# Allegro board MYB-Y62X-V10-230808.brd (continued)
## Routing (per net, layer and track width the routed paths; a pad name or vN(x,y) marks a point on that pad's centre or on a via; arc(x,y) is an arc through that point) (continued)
SOC_VOUT0_DATA12: length 75.7
  TOP w0.152: v2(137.71,47.5) 123.24,47.5 121.38,49.35 120.19,49.35 119.53,50.01 119.53,52.88 119.38,53.03 117.75,53.03 117.6,53.18 117.6,53.49 117.75,53.64 119.38,53.64 119.53,53.79 119.53,54.17 119.38,54.32 116.4,54.32 116.25,54.47 116.25,54.77 116.4,54.93 119.38,54.93 119.53,55.08 119.53,55.45 119.38,55.61 115.59,55.61 115.44,55.76 115.44,56.06 115.59,56.22 119.38,56.22 119.53,56.37 119.53,56.69 119.17,57.05 115.59,57.05 115.04,57.6 115.04,60.26 114.5,60.81 113.1,60.81 112.67,61.24 112.67,62 112.34,62.33 111.77,62.33 111.62,62.49 111.62,63.42 111.47,63.58 111.16,63.58 111.01,63.42 111.01,62.49 110.86,62.33 110.55,62.33 110.4,62.49 110.4,63.42 110.25,63.58 109.94,63.58 109.79,63.42 109.79,62.49 109.64,62.33 U43.97 ; R175.1 144.7,39.62 144.45,39.88 v2(143.43,39.88)
  BOTTOM w0.152: v2(143.43,39.88) 143.43,40.77 137.71,46.48 v2(137.71,47.5)
SOC_VOUT0_DATA13: length 76.9
  TOP w0.152: R176.1 145.59,41.27 144.95,41.91 142.97,41.91 142.81,42.06 142.81,42.65 142.66,42.8 142.36,42.8 142.2,42.65 142.2,42.06 142.05,41.91 141.75,41.91 141.59,42.06 141.59,42.65 141.44,42.8 141.14,42.8 140.98,42.65 140.98,42.06 140.83,41.91 140.53,41.91 140.37,42.06 140.37,42.65 140.22,42.8 139.92,42.8 139.77,42.65 139.77,42.06 139.61,41.91 139.31,41.91 139.16,42.06 139.16,42.65 139,42.8 138.7,42.8 138.55,42.65 138.55,42.06 138.39,41.91 138.09,41.91 137.94,42.06 137.94,42.65 137.78,42.8 137.11,42.8 136.95,42.65 v2(136.95,39.75) ; U43.L30 v2(106.6,52.32)
  BOTTOM w0.152: v2(106.6,52.32) 106.09,52.83 106.09,53.59 106.73,54.23 108.25,54.23 110.41,56.39 111.94,56.39 112.09,56.54 112.09,57.56 112.24,57.71 112.55,57.71 112.7,57.56 112.7,56.54 112.85,56.39 113.81,56.39 113.96,56.54 113.96,56.74 114.11,56.9 114.42,56.9 114.57,56.74 114.57,56.54 114.72,56.39 115.02,56.39 115.18,56.54 115.18,56.74 115.33,56.9 115.63,56.9 115.79,56.74 115.79,56.54 115.94,56.39 116.24,56.39 116.4,56.54 116.4,56.74 116.55,56.9 116.85,56.9 117.01,56.74 117.01,56.54 117.16,56.39 117.62,56.39 118.21,55.8 119.5,55.8 120.93,54.38 120.93,52.2 121.08,52.04 125.12,52.04 125.28,51.89 125.28,51.38 125.43,51.23 127.81,51.23 128.18,50.86 128.18,47.9 128.33,47.74 129,47.74 129.16,47.59 129.16,47.29 129,47.13 128.33,47.13 128.18,46.98 128.18,46.68 128.33,46.52 129,46.52 129.16,46.37 129.16,46.07 129,45.91 128.33,45.91 128.18,45.76 128.18,45.07 132.36,40.89 135.81,40.89 v2(136.95,39.75)
SOC_VOUT0_DATA14: length 75.3
  TOP w0.152: R177.1 v2(146.48,39.62) ; U43.94 112.67,59.33 113.97,58.04 113.97,54.64 117.14,51.46 117.98,51.46 118.13,51.31 118.13,46.78 118.76,46.15 118.76,45.39 118.91,45.24 119.22,45.24 119.37,45.39 119.37,46.15 119.52,46.3 119.83,46.3 119.98,46.15 119.98,45.39 120.13,45.24 120.44,45.24 120.59,45.39 120.59,46.15 120.74,46.3 121.05,46.3 121.2,46.15 121.2,45.39 121.35,45.24 121.66,45.24 121.81,45.39 121.81,46.15 121.96,46.3 122.26,46.3 122.42,46.15 122.42,45.39 122.57,45.24 122.87,45.24 123.03,45.39 123.03,46.15 123.18,46.3 123.48,46.3 123.64,46.15 123.64,45.39 123.79,45.24 124.09,45.24 124.25,45.39 124.25,46.15 124.4,46.3 124.7,46.3 124.86,46.15 124.86,45.39 125.01,45.24 125.31,45.24 125.47,45.39 125.47,46.15 125.62,46.3 125.92,46.3 126.07,46.15 126.07,45.39 126.23,45.24 126.53,45.24 126.68,45.39 126.68,46.15 126.84,46.3 127.14,46.3 127.29,46.15 127.29,45.39 127.45,45.24 127.75,45.24 127.9,45.39 127.9,46.15 128.06,46.3 128.36,46.3 128.51,46.15 128.51,45.39 128.67,45.24 128.97,45.24 129.12,45.39 129.12,46.15 129.28,46.3 129.58,46.3 129.73,46.15 129.73,45.39 129.88,45.24 130.19,45.24 130.34,45.39 130.34,46.15 130.49,46.3 130.8,46.3 130.95,46.15 130.95,45.39 131.1,45.24 131.41,45.24 131.56,45.39 131.56,46.15 131.71,46.3 132.02,46.3 132.17,46.15 132.17,45.39 132.32,45.24 132.63,45.24 132.78,45.39 132.78,46.15 132.93,46.3 133.24,46.3 133.39,46.15 133.39,45.39 133.54,45.24 134.24,45.24 134.39,45.39 134.39,46.02 134.84,46.48 v2(138.48,46.48)
  BOTTOM w0.152: v2(146.48,39.62) 145.33,39.62 v2(138.48,46.48)
SOC_VOUT0_DATA15: length 74.4
  TOP w0.152: R178.1 147.37,41.05 145.03,43.38 142.97,43.38 142.82,43.54 142.82,44.25 142.66,44.4 142.36,44.4 142.21,44.25 142.21,43.54 142.06,43.38 141.75,43.38 141.6,43.54 141.6,44.25 141.45,44.4 141.14,44.4 140.99,44.25 140.99,43.54 140.84,43.38 140.53,43.38 140.38,43.54 140.38,44.25 140.23,44.4 139.92,44.4 139.77,44.25 139.77,43.54 139.62,43.38 139.31,43.38 139.16,43.54 139.16,44.25 139.01,44.4 136.7,44.4 135.68,43.38 v2(135.68,39.75) ; U43.L28 99.87,48.9 v2(104.57,48.9)
  BOTTOM w0.152: v2(104.57,48.9) 111.04,55.37 116.18,55.37 116.71,54.84 118.97,54.84 119.93,53.87 119.93,51.61 120.46,51.08 124,51.08 124.94,50.14 125.57,50.14 125.88,49.83 125.88,47.96 126.85,46.99 126.85,44.93 132.03,39.75 v2(135.68,39.75)
SOC_VOUT0_DATA16/BOOTMODE08: length 75
  TOP w0.152: R179.1 v2(148.26,40.01) R197.1 ; v2(120.82,74.8) 114.73,74.8 109.2,80.33 U43.115
  BOTTOM w0.152: v2(148.26,40.01) 148.13,40.13 145.46,40.13 139.24,46.35 139.24,46.74 134.29,51.69 134.29,58.72 128.29,64.72 128.29,66.73 127.73,67.28 125.98,67.28 125.13,68.14 124.84,68.14 124.68,68.29 124.68,69.44 124.53,69.6 124.23,69.6 124.08,69.44 124.08,68.29 123.92,68.14 123.62,68.14 123.47,68.29 123.47,69.44 123.31,69.6 123.01,69.6 122.86,69.44 122.86,68.29 122.7,68.14 122.4,68.14 122.25,68.29 122.25,69.44 122.09,69.6 121.79,69.6 121.64,69.44 121.64,68.66 121.43,68.45 121.13,68.45 120.82,68.76 v2(120.82,74.8)
SOC_VOUT0_DATA17/BOOTMODE09: length 74.9
  TOP w0.152: R199.1 v2(149.27,40.01) R180.1 ; U43.113 109.16,78.33 113.2,74.3 v2(121.71,74.3)
  BOTTOM w0.152: v2(149.27,40.01) 148.76,40.51 145.67,40.51 139.67,46.51 139.67,46.94 134.79,51.82 134.79,58.96 128.75,65 128.75,67.72 128.01,68.45 125.6,68.45 125.32,68.73 125.32,69.85 125.07,70.1 121.87,70.1 121.71,70.26 121.71,70.57 121.87,70.72 125.19,70.72 125.35,70.88 125.35,71.18 125.19,71.33 121.87,71.33 121.71,71.49 v2(121.71,74.3)
SOC_VOUT0_DATA18/BOOTMODE10: length 74
  TOP w0.152: v2(122.6,73.79) 112.7,73.79 109.15,77.33 U43.112 ; R181.1 v2(150.29,40.01) R200.1
  BOTTOM w0.152: v2(122.6,73.79) 122.6,72.72 123.44,71.88 125.83,71.88 125.98,71.73 125.98,71.09 126.13,70.94 126.69,70.94 126.84,70.78 126.84,70.48 126.69,70.33 126.13,70.33 125.98,70.18 125.98,69.11 126.16,68.94 128.34,68.94 129.16,68.12 129.16,65.43 133.52,61.06 133.74,61.06 134.09,61.42 134.31,61.42 134.52,61.2 134.52,60.99 134.17,60.63 134.17,60.42 135.23,59.35 135.23,52.01 135.63,51.62 135.84,51.62 136.01,51.78 136.22,51.78 136.44,51.57 136.44,51.35 136.27,51.19 136.27,50.97 136.49,50.76 136.7,50.76 136.87,50.92 137.09,50.92 137.3,50.71 137.3,50.49 137.14,50.32 137.14,50.11 137.35,49.89 137.57,49.89 137.73,50.06 137.95,50.06 138.16,49.84 138.16,49.63 138,49.46 138,49.25 138.21,49.03 138.43,49.03 138.6,49.2 138.81,49.2 139.03,48.98 139.03,48.76 138.86,48.6 138.86,48.38 139.08,48.17 139.29,48.17 139.46,48.33 139.67,48.33 139.89,48.12 139.89,47.9 139.72,47.74 139.72,47.52 140.2,47.04 140.2,46.61 145.79,41.02 149.27,41.02 v2(150.29,40.01)
SOC_VOUT0_DATA19/BOOTMODE11: length 77.2
  TOP w0.152: U43.116 108.96,81.33 114.98,75.31 121.71,75.31 v2(123.24,73.79) ; R182.1 v2(151.3,40.01) R201.1
  BOTTOM w0.152: v2(123.24,73.79) 123.24,72.77 123.59,72.42 127.28,72.42 127.81,71.88 127.81,71.17 127.4,70.76 127.4,69.98 127.78,69.6 128.44,69.6 130.18,67.86 130.18,66.15 129.81,65.78 129.81,65.56 130.03,65.35 130.24,65.35 130.61,65.72 130.82,65.72 131.04,65.5 131.04,65.29 130.67,64.92 130.67,64.7 130.89,64.49 131.1,64.49 131.47,64.85 131.69,64.85 131.9,64.64 131.9,64.42 131.53,64.05 131.53,63.84 131.75,63.62 131.97,63.62 132.33,63.99 132.55,63.99 132.77,63.78 132.77,63.56 132.4,63.19 132.4,62.98 132.61,62.76 132.83,62.76 133.2,63.13 133.41,63.13 133.63,62.91 133.63,62.7 133.26,62.33 133.26,62.11 133.48,61.9 133.69,61.9 134.06,62.27 134.28,62.27 135.68,60.86 135.68,53.04 140.61,48.11 140.61,46.79 146,41.4 149.91,41.4 v2(151.3,40.01)
SOC_VOUT0_DATA20/BOOTMODE12: length 72
  TOP w0.152: R202.1 v2(152.32,40.01) R183.1 ; v2(141.04,46.99) 121.77,46.99 121.6,47.17 121.6,48.64 121.44,48.79 121.14,48.79 120.99,48.64 120.99,47.14 120.83,46.99 120.56,46.99 120.38,47.17 120.38,48.64 120.22,48.79 119.92,48.79 119.77,48.64 119.77,47.14 119.62,46.99 119.12,46.99 118.84,47.27 118.84,51.92 118.51,52.25 117.29,52.25 114.5,55.04 114.5,59.56 113.86,60.2 112.11,60.2 111.96,60.35 111.96,61.42 111.81,61.57 111.5,61.57 111.35,61.42 111.35,60.35 111.2,60.2 110.87,60.2 110.71,60.35 110.71,61.42 110.56,61.57 110.26,61.57 110.1,61.42 110.1,60.35 109.95,60.2 109.55,60.2 109.39,60.35 109.39,61.21 109.27,61.33 U43.96
  BOTTOM w0.152: v2(141.04,46.99) 142.08,45.95 142.82,45.95 146.99,41.78 150.54,41.78 v2(152.32,40.01)
SOC_VOUT0_DATA21/BOOTMODE13: length 73.8
  TOP w0.152: v2(129.21,72.39) 128.7,72.9 111.17,72.9 110.16,71.88 110.16,69.34 109.15,68.33 U43.103 ; R184.1 v2(153.34,40.01) R203.1
  BOTTOM w0.152: v2(129.21,72.39) 130.98,70.61 130.98,68.91 131.14,68.76 132.13,68.76 132.28,68.6 132.28,68.3 132.13,68.15 131.57,68.15 131.42,67.99 131.42,66.7 136.7,61.42 136.7,53.38 147.41,42.67 152.98,42.67 153.34,42.32 v2(153.34,40.01)
SOC_VOUT0_DATA22/BOOTMODE14: length 71.9
  TOP w0.152: v2(129.84,72.39) 128.9,73.33 U43.108 ; R185.1 v2(154.35,40.01) R204.1
  BOTTOM w0.152: v2(154.35,40.01) 154.35,42.65 153.82,43.18 147.62,43.18 137.21,53.59 137.21,61.59 132.91,65.89 132.91,66.5 132.76,66.66 132.1,66.66 131.95,66.81 131.95,67.11 132.1,67.27 132.76,67.27 132.91,67.42 132.91,68.88 132.42,69.38 132.05,69.38 131.62,69.81 131.62,70.61 v2(129.84,72.39)
SOC_VOUT0_DATA23/BOOTMODE15: length 73.6
  TOP w0.152: v2(128.57,72.39) 111.55,72.39 110.66,71.5 110.66,68.96 109.04,67.33 U43.102 ; R186.1 v2(155.37,40.01) R205.1
  BOTTOM w0.152: v2(155.37,40.01) 154.83,39.47 153.13,39.47 152.83,39.78 152.83,40.26 150.8,42.29 147.13,42.29 136.23,53.19 136.23,61.1 130.83,66.5 130.83,68.05 130.35,68.53 130.35,70.61 v2(128.57,72.39)
SOC_VOUT0_DE: length 72.9
  TOP w0.152: v2(112.59,52.86) 109.65,52.86 109.12,52.33 U43.87 ; R194.1 v2(140,26.54)
  BOTTOM w0.152: v2(140,26.54) 138.07,26.54 137.89,26.72 137.89,32.49 137.51,32.87 136.29,32.87 133.88,35.28 133.88,36.83 133.68,37.03 130.73,37.03 130.5,37.26 130.5,38.53 130.3,38.73 129.36,38.73 129.03,39.07 129.03,40.44 125.09,44.37 125.09,45.87 123.95,47.02 123.95,47.63 123.8,47.78 123.42,47.78 123.27,47.63 123.27,47.32 123.12,47.17 122.81,47.17 122.66,47.32 122.66,47.63 122.51,47.78 122.2,47.78 122.05,47.63 122.05,47.32 121.9,47.17 121.59,47.17 121.44,47.32 121.44,47.63 121.29,47.78 120.98,47.78 120.83,47.63 120.83,47.32 120.68,47.17 120.37,47.17 120.22,47.32 120.22,47.63 120.04,47.8 118.97,47.8 118.82,47.96 118.82,48.26 118.97,48.41 123.8,48.41 123.95,48.57 123.95,48.82 123.8,48.97 123.37,48.97 123.22,49.12 123.22,49.38 123.07,49.53 122.76,49.53 122.61,49.38 122.61,49.12 122.46,48.97 122.15,48.97 122,49.12 122,49.38 121.85,49.53 121.54,49.53 121.39,49.38 121.39,49.12 121.24,48.97 120.93,48.97 120.78,49.12 120.78,49.38 120.63,49.53 120.32,49.53 120.17,49.38 120.17,49.12 120.02,48.97 118.16,48.97 117.73,49.4 117.73,53.02 117.57,53.17 116.04,53.17 115.36,53.85 111.25,53.85 111.1,53.7 111.1,53.01 111.25,52.86 v2(112.59,52.86)
SOC_VOUT0_HSYNC: length 74
  TOP w0.152: R196.1 v2(140,25.65) ; U43.88 v2(113.71,53.33)
  BOTTOM w0.152: v2(113.71,53.33) 115.34,53.33 116.02,52.65 116.91,52.65 117.06,52.5 117.06,47.14 117.7,46.51 119.64,46.51 119.79,46.35 119.79,45.57 119.94,45.42 120.25,45.42 120.4,45.57 120.4,46.33 120.58,46.51 120.86,46.51 121.01,46.35 121.01,45.57 121.16,45.42 121.47,45.42 121.62,45.57 121.62,46.33 121.8,46.51 122.08,46.51 122.23,46.35 122.23,45.57 122.38,45.42 122.69,45.42 122.84,45.57 122.84,46.33 123.02,46.51 123.57,46.51 123.95,46.13 123.95,44.72 128.24,40.43 128.24,40.06 128.09,39.91 126.51,39.91 126.36,39.76 126.36,39.45 126.51,39.3 127.96,39.3 128.6,38.66 128.6,36.7 128.75,36.55 129.1,36.55 129.25,36.7 129.25,38.13 129.4,38.28 129.71,38.28 129.86,38.13 129.86,36.7 130.01,36.55 132.71,36.55 133.27,35.99 133.27,35.18 136.14,32.31 136.98,32.31 137.46,31.83 137.46,25.76 137.21,25.5 134.31,25.5 134.16,25.35 134.16,24.79 134.31,24.64 137.44,24.64 137.97,25.17 139.52,25.17 v2(140,25.65)
SOC_VOUT0_PCLK: length 73.1
  TOP w0.152: U43.89 v2(112.7,54.33) ; R198.1 139.21,35.43 139.05,35.28 139.05,35 138.9,34.85 138.6,34.85 138.42,35.03 138.42,35.59 138.27,35.74 137.86,35.74 137.71,35.59 137.71,34.82 137.55,34.67 137.27,34.67 137.05,34.9 137.05,36.73 137.2,36.88 139.47,36.88 139.65,37.06 139.65,37.41 139.5,37.57 136.55,37.57 136.39,37.41 136.39,33.6 136.24,33.45 135.94,33.45 135.76,33.63 135.76,37.44 135.61,37.59 135.3,37.59 135.15,37.44 135.15,33.6 135,33.45 134.57,33.45 134.41,33.6 v2(134.41,35.43)
  BOTTOM w0.152: v2(134.41,35.43) 134.44,35.46 134.44,38.2 134.29,38.35 131.87,38.35 125.62,44.6 125.62,46.2 124.53,47.29 124.53,48.97 123.55,49.95 119.55,49.95 119.11,49.5 118.31,49.5 118.16,49.66 118.16,51.3 118.31,51.45 118.87,51.45 119.02,51.6 119.02,51.91 118.87,52.06 118.31,52.06 118.16,52.21 118.16,52.52 118.31,52.67 118.87,52.67 119.02,52.82 119.02,53.26 118.59,53.7 116.15,53.7 115.51,54.33 v2(112.7,54.33)
SOC_VOUT0_VSYNC: length 74.1
  TOP w0.152: v2(114.85,52.83) 112.35,55.33 U43.90 ; R195.1 v2(140,24.77)
  BOTTOM w0.152: v2(140,24.77) 138.3,24.77 137.74,24.21 134.01,24.21 133.68,24.54 133.68,25.73 134.01,26.06 136.6,26.06 137.08,26.54 137.08,31.29 136.6,31.78 133.55,31.78 132.85,32.48 132.85,34.91 132.19,35.56 125.73,35.56 125.22,36.07 125.22,36.61 125.37,36.76 127.12,36.76 127.28,36.92 127.28,37.22 127.12,37.37 125.37,37.37 125.22,37.53 125.22,37.83 125.37,37.98 127.12,37.98 127.28,38.14 127.28,38.44 127.12,38.59 125.37,38.59 125.22,38.75 125.22,40.59 125.37,40.74 126.49,40.74 126.64,40.9 126.64,41.2 126.49,41.35 125.37,41.35 125.22,41.51 125.22,42.38 122.69,44.91 118.28,44.91 116.53,46.66 116.53,51.16 v2(114.85,52.83)
SOC_WKUP_UART0_RXD: length 216
  TOP w0.152: v2(79.8,49.28) 79.8,49.63 79.65,49.78 U43.L20 ; U46.8 17.03,110.35 17.29,110.08 v2(17.29,105.51)
  ART03 w0.152: v2(114.73,81.28) 114.85,81.15 119.81,81.15 125.6,86.94 125.6,89.33 124.56,90.37 120.64,90.37 119.81,89.53 113.58,89.53 111.81,91.31 111.81,92.63 110.44,94.01 108.86,94.01 105.71,97.16 103.9,97.16 97.89,103.17 97.89,106.48 94.53,109.83 94.53,112.52 93.65,113.41 65.07,113.41 62.02,110.36 33.96,110.36 29.1,105.51 v2(17.29,105.51) ; v2(79.8,49.28) 90.8,49.28 91.87,48.21 102.36,48.21 105.08,50.93 105.08,72.06 104.42,72.72 104.42,78.21 v2(105.71,79.5)
  BOTTOM w0.152: v2(114.73,81.28) 113.58,80.14 106.35,80.14 v2(105.71,79.5)
SOC_WKUP_UART0_TXD: length 191.7
  TOP w0.152: v2(105.61,55.7) 105.61,53.87 U43.L31 ; v2(17.98,106.07) 17.98,110.52 17.5,111 14.65,111 14.01,110.35 U46.1
  ART03 w0.152: v2(17.98,106.07) 28.77,106.07 33.83,111.12 61.9,111.12 64.69,113.92 94.05,113.92 95.12,112.85 95.12,110.13 98.52,106.73 98.52,103.2 104.06,97.66 105.84,97.66 108.99,94.51 111.02,94.51 112.57,92.96 112.57,91.44 113.84,90.17 119.68,90.17 120.44,90.93 124.76,90.93 126.13,89.56 v2(126.13,78.46)
  BOTTOM w0.152: v2(126.13,78.46) 125.78,78.11 111.96,78.11 108.07,74.22 108.07,73.23 105.05,70.2 105.05,56.27 v2(105.61,55.7)
USB0CC1: length 8.4
  TOP w0.203: 57.83,17.14 58.01,17.33 U29.1
  TOP w0.254: 57.83,17.14 57.58,16.89 54.91,16.89 54.4,16.38 54.4,14.8 54.15,14.55 C158.1 53.66,14.53 R314.1
USB0CC2: length 5.6
  TOP w0.203: U29.2 58.41,17.45
  TOP w0.254: R315.1 C160.1 57.83,14.55 57.58,14.8 57.58,16 58.41,16.84 58.41,17.45
USB_5G_DM: length 130.6
  TOP w0.155: U28.17 130.11,24.45 130.19,24.36 130.19,24.15 129.53,23.48 128.03,23.48 127.39,24.12 127.39,24.98 126.95,25.42 125.82,25.42 v2(125.65,25.59)
  ART03 w0.137: v2(28.66,43.81) 28.49,43.65 28.49,43.47 28.63,43.33 34.23,43.33 34.71,43.81 36.08,43.81 36.23,43.97 36.62,43.97 36.78,43.81 37.19,43.81 37.34,43.97 37.74,43.97 37.89,43.81 38.29,43.81 38.44,43.97 38.84,43.97 38.99,43.81 39.16,43.81 39.34,43.99 39.71,43.99 39.89,43.81 40.26,43.81 40.44,43.99 40.81,43.99 40.98,43.81 41.35,43.81 41.53,43.99 41.9,43.99 42.08,43.81 44.65,43.81 44.8,43.97 45.2,43.97 45.35,43.81 45.75,43.81 45.9,43.97 46.3,43.97 46.45,43.81 57.1,43.81 59.25,45.97 61.95,45.97 63.8,44.12 63.8,37.21 65.23,35.79 73.34,35.79 75.5,37.95 80.67,37.95 82.22,36.4 88.72,36.4 89.38,35.74 96.39,35.74 96.97,36.32 99.36,36.32 100.38,35.31 110.16,35.31 110.89,34.57 110.89,33.4 111.1,33.2 118.69,33.2 125.04,26.85 125.04,25.56 125.18,25.42 125.49,25.42 v2(125.65,25.59)
  BOTTOM w0.155: v2(28.66,43.81) 28.49,43.98 28.49,46.74 29.41,47.65 29.41,49.29 29.5,49.38 J19.9
USB_5G_DP: length 130.7
  TOP w0.155: U28.18 130.61,24.45 130.52,24.36 130.52,24.01 129.67,23.16 127.89,23.16 127.07,23.98 127.07,24.84 126.81,25.1 125.82,25.1 v2(125.65,24.93)
  ART03 w0.137: v2(125.65,24.93) 125.49,25.1 125.04,25.1 124.71,25.42 124.71,26.71 118.55,32.87 110.96,32.87 110.56,33.27 110.56,34.43 110.02,34.98 100.24,34.98 99.23,35.99 97.11,35.99 96.52,35.41 89.25,35.41 88.58,36.07 82.09,36.07 80.54,37.62 75.64,37.62 73.48,35.46 65.09,35.46 63.47,37.08 63.47,43.98 61.81,45.65 59.39,45.65 57.23,43.49 34.85,43.49 34.36,43 28.5,43 28.17,43.33 28.17,43.65 v2(28,43.81)
  BOTTOM w0.155: v2(28,43.81) 28.17,43.98 28.17,46.87 29.09,47.79 29.09,49.29 29,49.38 J19.7
USB_HUB_RST: length 45.7
  TOP w0.152: v2(138.98,31.24) 138.41,31.24 R487.1 ; U42.6 137.02,67.64 135.94,66.55 135.94,63.25 v2(138.86,60.33)
  ART03 w0.152: v2(138.98,31.24) 139.49,31.75 139.49,33.15 138.86,33.78 138.86,34.92 140.38,36.45 140.38,42.95 143.68,46.25 v2(143.68,47.78)
  BOTTOM w0.152: v2(143.68,47.78) 138.86,52.6 v2(138.86,60.33)
USB_I2C_SCL: length 2.3
  TOP w0.152: U29.8 58.01,20.08 v2(57.77,20.32) R454.2
  BOTTOM w0.152: R454.2 v2(57.77,20.32)
USB_I2C_SDA: length 2.3
  TOP w0.152: R494.2 v2(58.66,20.32) 58.41,20.08 U29.7
  BOTTOM w0.152: R494.2 v2(58.66,20.32)
USB_UART_DM: length 4.8
  TOP w0.155: U19.4 71.36,17.19 71.27,17.11 71.27,14.03 71.61,13.69 L6.1
USB_UART_DP: length 4.8
  TOP w0.155: U19.3 70.86,17.19 70.94,17.11 70.94,14.03 70.61,13.69 L6.4
USBA0_DM: length 11.8
  TOP w0.155: J16.A2 133.5,15.94 133.5,17.69 133.17,18.03 133.17,19.6 D27.2 133.17,20.67 133.17,22.24 131.69,23.72 131.69,24.36 131.61,24.45 U28.20
USBA0_DP: length 11.8
  TOP w0.155: U28.21 132.11,24.45 132.02,24.36 132.02,23.85 133.5,22.38 133.5,20.67 D28.2 133.5,19.6 133.5,18.16 133.83,17.83 133.83,15.94 J16.A3
USBA1_DM: length 17.1
  TOP w0.155: J16.B2 133.5,13.32 133.5,13.7 133.85,14.04 135.56,14.04 135.74,14.23 135.74,19.6 D30.2 135.77,20.7 135.77,22.31 135.04,23.04 134.16,23.04 133.19,24.01 133.19,24.36 133.11,24.45 U28.23
USBA1_DP: length 17.1
  TOP w0.155: J16.B3 133.83,13.32 133.83,13.56 133.98,13.72 135.69,13.72 136.07,14.09 136.07,19.6 D29.2 136.09,20.64 136.09,22.45 135.18,23.37 134.3,23.37 133.52,24.15 133.52,24.36 133.61,24.45 U28.24
USBC_ID: length 15.5
  TOP w0.152: v2(55.99,20.32) R309.2 56.82,19.56 56.98,19.4 U29.9 ; v2(61.13,27.05) 61.13,28.65 60.76,29.02 R319.1
  ART03 w0.152: v2(61.13,27.05) 59.31,27.05 58.09,25.83 58.09,24.64 55.99,22.54 v2(55.99,20.32)
USER_LED: length 92.3
  TOP w0.152: v2(127.85,79.12) 129.4,77.57 137.66,77.57 142.62,72.62 142.62,67.74 141.21,66.33 U42.8 ; D54.2 v2(97.84,116.08)
  ART03 w0.152: v2(127.85,79.12) 128.44,79.72 128.44,87.88 131.24,90.68 131.24,93.73 128.82,96.14 108.81,96.14 105.41,99.54 103.5,99.54 99.77,103.28 99.77,107.01 97.84,108.94 v2(97.84,116.08)
USIM1_CLK: length 79.9
  ART03 w0.152: v2(63.57,102.21) 55.27,102.21 51.71,98.65 51.71,80.14 50.75,79.17 v2(50.75,76.23)
  BOTTOM w0.152: J19.32 35.25,62.65 38.49,65.9 48.04,65.9 48.75,66.61 48.75,75.47 49.5,76.23 v2(50.75,76.23) ; v2(63.57,102.21) 64.87,100.91 70.3,100.91 70.46,101.07 73.99,101.07 R327.2
USIM1_DATA: length 81.1
  ART03 w0.152: v2(64,102.72) 62.38,102.72 61.79,103.3 60.81,103.3 60.66,103.15 60.66,102.97 60.5,102.82 60.2,102.82 60.05,102.97 60.05,103.15 59.89,103.3 59.59,103.3 59.44,103.15 59.44,102.97 59.28,102.82 58.98,102.82 58.83,102.97 58.83,103.15 58.67,103.3 58.37,103.3 58.22,103.15 58.22,102.97 58.06,102.82 57.76,102.82 57.61,102.97 57.61,103.15 57.45,103.3 57.15,103.3 57,103.15 57,102.97 56.85,102.82 56.54,102.82 56.39,102.97 56.39,103.15 56.24,103.3 55.7,103.3 51.23,98.83 51.23,80.42 50.24,79.43 v2(50.24,75.77)
  BOTTOM w0.152: R325.2 72.85,101.57 70.25,101.57 70.02,101.35 65.38,101.35 v2(64,102.72) ; v2(50.24,75.77) 49.6,75.77 49.25,75.41 49.25,66.34 48.3,65.4 38.7,65.4 35.75,62.45 J19.34
USIM1_DET: length 87.7
  ART03 w0.152: v2(52.55,76) 52.55,98.07 55.39,100.91 64.08,100.91 66.33,103.16 68.36,103.16 68.58,103.38 68.58,104.61 68.73,104.77 69.19,104.77 69.34,104.92 69.34,105.22 69.19,105.37 68.37,105.37 68.22,105.53 68.22,106.65 68.37,106.81 69.59,106.81 69.74,106.65 69.74,105.92 69.9,105.77 70.2,105.77 70.35,105.92 70.35,106.65 70.5,106.81 70.81,106.81 70.96,106.65 70.96,105.92 71.11,105.77 71.42,105.77 71.57,105.92 71.57,106.65 71.72,106.81 v2(75.15,106.81)
  BOTTOM w0.152: v2(52.55,76) 53.54,75.01 53.54,64.11 53.14,63.71 53.14,63.5 53.5,63.14 53.5,62.93 53.28,62.71 53.07,62.71 52.71,63.07 52.5,63.07 52.28,62.85 52.28,62.64 52.64,62.28 52.64,62.06 52.42,61.85 52.21,61.85 51.85,62.21 51.63,62.21 51.42,61.99 51.42,61.77 51.78,61.42 51.78,61.2 51.56,60.99 51.34,60.99 50.99,61.34 50.77,61.34 50.56,61.13 50.56,60.91 50.91,60.56 50.91,60.34 50.7,60.12 50.48,60.12 50.13,60.48 49.91,60.48 49.63,60.2 44.37,60.2 43.75,59.58 J19.66 ; J17.4 75.17,106.82 v2(75.15,106.81)
USIM1_RST: length 81
  ART03 w0.152: v2(51.2,76.71) 51.96,76.71 52.12,76.86 52.12,77.32 51.96,77.48 51.51,77.48 51.35,77.63 51.35,77.93 51.51,78.09 51.96,78.09 52.12,78.24 52.12,78.54 51.96,78.69 51.51,78.69 51.35,78.85 51.35,79.15 51.51,79.3 51.96,79.3 52.12,79.46 52.12,98.36 55.44,101.68 63.9,101.68 v2(64.92,102.69)
  BOTTOM w0.152: J19.30 34.75,62.86 38.29,66.4 47.9,66.4 48.25,66.74 48.25,68.91 47.65,69.51 47.65,69.87 47.8,70.02 48.03,70.02 48.18,70.18 48.18,70.48 48.03,70.63 47.8,70.63 47.65,70.79 47.65,71.09 47.8,71.24 48.03,71.24 48.18,71.4 48.18,71.7 48.03,71.85 47.8,71.85 47.65,72 47.65,72.31 47.8,72.46 48.03,72.46 48.18,72.61 48.18,72.92 48.03,73.07 47.8,73.07 47.65,73.22 47.65,76.3 48.05,76.71 v2(51.2,76.71) ; v2(64.92,102.69) 64.92,102.67 65.83,101.75 69.73,101.75 R326.2
USIM2_CLK: length 97.5
  ART03 w0.152: v2(90.57,101.04) 89.99,101.63 89.99,103.61 89.07,104.52 87.63,104.52 87.37,104.27 77.11,104.27 75.97,103.12 70.63,103.12 69.24,101.73 67.13,101.73 64.84,99.44 57.55,99.44 54.23,96.12 54.23,75.51 v2(52.62,73.91)
  BOTTOM w0.152: v2(52.62,73.91) 51.48,72.77 51.48,64.47 48.73,61.72 43.27,61.72 42.15,60.6 39.06,60.6 38.25,59.79 J19.44 ; R333.2 93.83,101.22 92.76,101.22 91.99,100.46 91.16,100.46 v2(90.57,101.04)
USIM2_DATA: length 98.7
  ART03 w0.152: v2(90.57,101.75) 90.57,104.01 89.53,105.05 87.52,105.05 87.19,104.72 74.77,104.72 74.59,104.55 74.59,104.01 74.44,103.86 74.13,103.86 73.98,104.01 73.98,104.57 73.83,104.72 71.45,104.72 68.92,102.2 66.86,102.2 64.59,99.92 56.51,99.92 55.16,98.58 55.16,97.79 53.72,96.34 53.72,75.77 v2(52.62,74.68)
  BOTTOM w0.152: v2(52.62,74.68) 51,73.05 51,64.67 48.56,62.23 42.97,62.23 42.69,62.51 40.19,62.51 37.75,60.07 J19.42 ; v2(90.57,101.75) 91.23,101.09 92.05,101.09 R335.2
USIM2_DET: length 105.2
  ART03 w0.152: v2(94.28,106.81) 90.21,106.81 90.06,106.65 90.06,106.15 89.91,105.99 89.6,105.99 89.45,106.15 89.45,106.65 89.3,106.81 88.52,106.81 86.89,105.18 75.38,105.18 75.23,105.33 75.23,106.02 75.08,106.17 74.77,106.17 74.62,106.02 74.62,105.33 74.47,105.18 74.16,105.18 74.01,105.33 74.01,106.02 73.86,106.17 73.55,106.17 73.4,106.02 73.4,105.33 73.25,105.18 72.94,105.18 72.79,105.33 72.79,106.02 72.64,106.17 72.34,106.17 72.18,106.02 72.18,105.33 72.03,105.18 71.12,105.18 68.56,102.63 66.66,102.63 64.46,100.43 56.41,100.43 55.85,99.88 55.64,99.88 55.38,100.13 55.17,100.13 54.95,99.91 54.95,99.7 55.21,99.45 55.21,99.23 54.53,98.55 54.53,97.92 53.21,96.6 53.21,75.99 v2(52.58,75.36)
  BOTTOM w0.152: v2(94.28,106.81) 94.85,107.38 J18.4 ; v2(52.58,75.36) 50.49,73.28 50.49,64.88 48.35,62.74 44.24,62.74 43.76,63.22 40.19,63.22 37.25,60.28 J19.40
USIM2_RST: length 98.7
  ART03 w0.152: v2(89.96,100.84) 89.53,101.27 89.53,102.54 88.69,103.38 82.19,103.38 81.05,102.23 80.43,102.23 80.15,102.51 80.15,103.58 80,103.73 79.69,103.73 79.54,103.58 79.54,102.51 79.39,102.36 78.14,102.36 77.99,102.51 77.99,103.48 77.83,103.63 77.53,103.63 77.38,103.48 77.38,102.51 77.22,102.36 73.07,102.36 72.44,101.73 69.92,101.73 69.41,101.22 67.31,101.22 65.02,98.93 60.95,98.93 60.8,98.78 60.8,98.53 60.65,98.37 60.35,98.37 60.19,98.53 60.19,98.78 60.04,98.93 59.74,98.93 59.58,98.78 59.58,98.53 59.43,98.37 59.13,98.37 58.97,98.53 58.97,98.78 58.82,98.93 57.65,98.93 54.71,95.99 54.71,90 54.86,89.85 55.06,89.85 55.22,89.7 55.22,89.39 55.06,89.24 54.86,89.24 54.71,89.09 54.71,88.78 54.86,88.63 55.06,88.63 55.22,88.48 55.22,88.17 55.06,88.02 54.86,88.02 54.71,87.87 54.71,75.23 v2(52.62,73.15)
  BOTTOM w0.152: R332.2 v2(89.96,100.84) ; v2(52.62,73.15) 51.99,72.52 51.99,64.26 48.94,61.21 43.48,61.21 42.31,60.05 39.14,60.05 38.75,59.66 J19.46
W_DISABLE1_N: length 13.1
  BOTTOM w0.152: J19.8 29.25,54.11 31.16,52.2 31.16,47.5 30.27,46.61 R336.2
WAKE_ON_WAN_N: length 3.1
  BOTTOM w0.152: J19.23 33,48.2 TP20.1
WWAN_LED_N: length 135.3
  TOP w0.152: v2(94.03,112.27) 94.03,115.79 D55.2
  ART03 w0.152: v2(16.18,62.87) 14.19,64.85 14.19,82.09 17.17,85.06 18.49,85.06 21.94,88.52 21.94,90.68 32.86,101.6 44.88,101.6 53.01,109.73 66.53,109.73 68.56,111.76 91.36,111.76 91.87,112.27 v2(94.03,112.27)
  BOTTOM w0.152: v2(16.18,62.87) 18,61.04 28.29,61.04 29.75,59.58 J19.10
N19629412: length 2.5
  TOP w0.254: U27.14 45.5,19.06 44.62,18.19 C321.1
N19629418: length 2.9
  TOP w0.254: U27.13 45,19.26 C322.1
N19629536: length 2.9
  TOP w0.254: J14.3 44.24,3.57 R570.1
N19629600: length 2.1
  TOP w0.254: U27.10 43.5,18.94 v1(43.23,18.67)
  BOTTOM w0.381: C131.1 43.16,18.74 v1(43.23,18.67)
N19629602: length 2.4
  TOP w0.254: U27.18 47.5,20.72 47.85,20.37 v1(47.85,20.07)
  BOTTOM w0.381: v1(47.85,20.07) 47.85,20.18 47.47,20.56 C132.1
N19629628: length 2
  TOP w0.254: U27.31 43.5,25.13 v1(43.35,25.27)
  BOTTOM w0.254: v1(43.35,25.27) 43.35,25 R299.1
N20386876: length 4.1
  BOTTOM w0.152: R152.1 162.44,47.65 J9.9
N20386882: length 3.5
  BOTTOM w0.152: R150.1 165.19,46.15 J9.6
N20386885: length 3.3
  BOTTOM w0.152: R151.1 164.8,46.65 J9.7
N20386918: length 3.2
  BOTTOM w0.152: J9.2 164.46,44.15 R148.1
N20390587: length 2.6
  TOP w0.152: R132.1 R127.1 16.73,92.23 Q4.1
N20390701: length 7.3
  TOP w0.381: Q4.3 18.72,91.57 18.21,91.06 16.94,91.06 16.3,90.42 R108.2 R112.2
N20390757: length 5.3
  TOP w0.381: Q3.2 19.33,88.16 18.33,89.15 17.19,89.15 16.75,88.71 R108.1
  BOTTOM w0.381: v2(19.73,87.02) 19.73,87.56 C78.1
N20390883: length 5.7
  TOP w0.381: Q3.1 v2(17.75,87.25) 15.67,87.25 15.29,87.63 R112.1
  BOTTOM w0.381: v2(17.75,87.25) 17.75,87.61 C78.2
N20656670: length 1.6
  TOP w0.254: R288.1 49.87,23.17 Y2.3
N21392969: length 4
  TOP w0.152: U33.14 93.35,30.56 93.81,30.1 93.81,29.82 v2(94.45,29.18) R346.2
  BOTTOM w0.152: R346.2 v2(94.45,29.18)
N21392972: length 3.6
  TOP w0.152: U33.15 93.59,30.96 v2(94.47,30.07) R347.2
  BOTTOM w0.152: R347.2 v2(94.47,30.07)
N21393016: length 5.9
  TOP w0.152: R360.2 84.67,37.45 85.61,36.51 87.87,36.51 88.47,35.91 U33.34
N21393026: length 4.9
  TOP w0.203: R362.1 83.36,28.19 84.41,29.24 85.68,29.24 86.59,30.16 U33.48
N21393171: length 8.7
  TOP w0.508: C202.1 C203.1 88.73,21.97 89.24,21.46 J22.5 89.24,18.01 J22.6
N21406011: length 5.9
  TOP w0.152: U37.34 111.77,35.85 111.17,36.45 108.94,36.45 107.96,37.43 R395.2
N21406021: length 4.9
  TOP w0.203: R397.1 107.06,28.19 108.56,29.69 109.46,29.69 109.92,30.16 U37.48
N21406166: length 8.8
  TOP w0.508: J23.6 111.93,18.01 J23.5 111.93,21.3 111.39,21.84 C222.1 C221.1
N21450803: length 2.7
  TOP w0.152: SW3.2 130.86,43.74 R231.2
N21450805: length 2.7
  TOP w0.152: SW3.3 132.13,43.74 R227.2
N21473108: length 6.5
  TOP w0.152: Y3.1 122.22,27.56 123.11,27.56 123.69,28.14 C147.1 125.05,27.34 U28.11
N21476694: length 4.2
  TOP w0.152: Y3.3 123.7,27.24 C146.1 124.32,27.24 124.72,26.84 U28.12
N21477956: length 3
  TOP w0.152: U28.34 136.29,31.34 136.7,31.75 R306.2 R487.2
N21522281: length 6.8
  BOTTOM w0.152: R326.1 69.77,103.69 69.77,104.83 C182.1 D32.2 71.36,105.41 J17.2
N21522507: length 7.7
  BOTTOM w0.152: J17.7 72.63,105.4 D34.2 C184.1 74.15,104.77 74.15,103.75 R325.1 R322.2
N21526256: length 7.9
  BOTTOM w0.152: J17.3 73.9,106.83 TP16.1 74.72,106 D33.2 C183.1 75.93,105.34 76.45,104.83 76.45,103.58 76.05,103.18 R327.1
N21526274: length 7.7
  BOTTOM w0.152: J18.7 92.31,105.4 D38.2 C199.1 93.84,104.77 93.84,103.75 R335.1 R331.2
N21544762: length 8.4
  BOTTOM w0.508: J17.1 68.82,106.87 69.26,106.43 D31.2 C175.1 C176.1 66.93,105.34 66.42,104.83 66.42,103.69 66.93,103.18 R323.2
N21577420: length 3.1
  TOP w0.254: C171.1 36.75,67.18 36.41,66.85 36.41,66.35 36.67,66.1 U31.1
N21577513: length 3
  TOP w0.254: U31.4 40.94,64.2 R329.1 R324.2
N21577585: length 4
  TOP w0.254: U31.3 35.1,64.2 R330.1 C177.2 R328.2
N21670486: length 11.1
  TOP w0.152: D44.2 161.84,18.1 C239.1 D45.2 162.44,19.27 S1.3 S1.4
N21676766: length 11.3
  TOP w0.152: D46.2 161.72,26.04 C241.1 D47.2 164.71,27.3 S2.3 S2.4
N21683802: length 4.2
  TOP w0.152: U23.3 R266.2 R269.2
N21683845: length 4.7
  TOP w0.508: U23.12 132.95,106.62 131.68,107.89 R270.1 R267.2
N21683857: length 3.3
  TOP w0.152: U23.6 R268.2
N21683901: length 4.5
  TOP w0.508: U23.13 131.68,106.49 130.79,107.38 R272.1 R275.1
N21683929: length 5.5
  TOP w0.152: U23.4 U23.5 133.08,95.55 R274.2 R276.1
N21684314: length 4.2
  TOP w0.152: U25.3 R278.2 R283.2
N21684387: length 3.3
  TOP w0.152: U25.6 R280.2
N21684482: length 5.5
  TOP w0.152: U25.4 U25.5 120.38,95.55 R285.2 R287.1
N21714485: length 4.4
  TOP w0.508: U25.12 120.25,106.75 119.61,107.38 R281.1 R279.2
N21714524: length 4.3
  TOP w0.508: U25.13 118.98,106.75 118.73,107 R284.1 R286.1
N21848668: length 2.2
  TOP w0.254: C138.1 133.11,35.79 U28.38
N21848671: length 2.5
  TOP w0.152: R302.1 132.11,35.01 U28.40
N21849105: length 2.1
  TOP w0.254: U28.48 128.11,35.96 R300.2
N21849965: length 2.4
  TOP w0.152: U28.39 132.61,35.4 R301.2
N21885565: length 2.8
  TOP w0.254: R3.2 38.75,77.18 U1.7
N21885634: length 6.1
  TOP w0.254: R4.2 R6.1 41.04,79.47 41.04,79.98 40.55,80.48 U1.9
N21885693: length 3.6
  TOP w0.254: U1.8 39.2,78.95 40.18,77.98 TP3.1
N21885737: length 1
  TOP w0.381: R7.2 44.94,78.74 C19.1
N21885739: length 5.6
  TOP w0.254: U1.11 41.71,81.38 42.57,80.52 R9.1 R8.2 C19.2
N21885780: length 2.8
  TOP w0.254: U1.10 41.04,80.93 TP5.1
N21885830: length 3.2
  TOP w0.254: C20.1 42.72,81.83 U1.12
N21893632: length 4.2
  TOP w0.254: U1.13 39.2,82.7 39.53,83.03 42.73,83.03 C9.1
N21900346: length 3.7
  TOP w0.305: U3.7 55.58,39.47 R20.1 R18.2 C37.2
N22230603: length 3
  TOP w0.381: Y2.1 51.79,21 R289.2 C126.1
N22232243: length 2.4
  BOTTOM w0.381: Y1.1 158.52,47.57 C86.1 R149.2
N22247036: length 2.6
  TOP w0.152: U19.9 73.01,19.43 75.24,19.43 R248.2
N22324946: length 18.3
  TOP w0.155: J15.A6 55.76,8.15 55.84,8.23 55.84,8.59 v2(55.68,8.76) 55.84,8.93 55.84,9.69 D23.2 55.31,10.23 55.86,10.79 55.86,12.32 L9.3 ; J15.B6 56,5.03 55.91,4.95 55.91,3.66 v2(56.08,3.5)
  BOTTOM w0.155: v2(55.68,8.76) 55.84,8.93 55.84,9.68 55.69,9.83 55.17,9.83 54.86,9.52 54.86,7.85 55.18,7.53 55.37,7.53 55.51,7.67 55.7,7.67 55.84,7.53 55.84,7.34 55.7,7.2 55.7,7.01 55.91,6.8 55.91,6.57 56.05,6.44 56.15,6.44 56.28,6.3 56.28,6.11 56.15,5.97 56.05,5.97 55.91,5.83 55.91,3.66 v2(56.08,3.5)
N22324958: length 18.3
  TOP w0.155: L9.2 56.19,12.32 56.19,10.74 D24.2 56.17,9.69 56.17,8.93 v2(56.34,8.76) 56.17,8.59 56.17,8.23 56.26,8.15 J15.A7 ; v2(55.42,3.5) 55.58,3.66 55.58,4.95 55.5,5.03 J15.B7
  BOTTOM w0.155: v2(56.34,8.76) 56.17,8.93 56.17,9.81 55.83,10.16 55.04,10.16 54.53,9.65 54.53,7.72 55.58,6.66 55.58,3.66 v2(55.42,3.5)
N22324997: length 1.6
  TOP w0.152: R310.2 59.86,19.68 59.17,19 U29.5
N22325047: length 1.6
  TOP w0.203: U29.11 57,18.6 56.82,18.41 56.11,18.41 R311.2
N22325067: length 2.4
  TOP w0.203: R313.1 R312.2 59.86,17.91 59.57,18.2 U29.3
N22325125: length 7.2
  TOP w0.254: R314.2 54.15,12.51 54.4,12.26 54.4,10.48 54.15,10.23 D25.2 53.66,9.51 54.02,9.14 54.28,9.14 55.26,8.16 J15.A5
N22325136: length 10.6
  TOP w0.254: D26.2 v2(57.83,10.23) 57.83,12.03 R315.2 ; J15.B5 v2(56.5,4.64)
  BOTTOM w0.381: v2(56.5,4.64) 57.2,5.33 57.2,8.89 57.83,9.53 v2(57.83,10.23)
N22325338: length 6.5
  TOP w0.381: R317.1 R316.2 55.36,28.44 Q5.3 57.2,26.98 57.83,26.35 U30.4
N22325344: length 3.8
  TOP w0.152: U30.3 61.53,26.35 61.77,26.59 v2(61.77,27.05)
  BOTTOM w0.152: R318.2 61.51,26.29 61.77,26.54 v2(61.77,27.05)
N22325474: length 1.6
  TOP w0.152: Q5.1 59.18,30.33 R319.2
N22325526:
  vias: v1(124.33,19.68) v1(124.91,19.68) v1(125.47,19.68)
N22325538:
  vias: v1(130.58,17.96) v1(131.16,17.96) v1(131.72,17.96)
N22348627: length 4.6
  BOTTOM w0.152: R137.2 17.29,41.94 16.46,41.1 J6.27
N22348634: length 4.4
  BOTTOM w0.152: J6.28 16.8,40.6 17.24,41.05 R139.2
N22348696: length 4.8
  BOTTOM w0.152: J6.36 16.66,36.6 18.06,38 R144.2
N22355541: length 4
  BOTTOM w0.152: R138.2 16.8,69.93 J5.27
N22355547: length 3.8
  BOTTOM w0.152: J5.28 17.19,69.43 R140.2
N22355619: length 4
  BOTTOM w0.152: R146.2 17.29,64.26 16.13,65.43 J5.36
N22387016: length 4.2
  TOP w0.254: U2.13 34.89,36.98 35.21,37.31 38.41,37.31 C21.1
N22387130: length 2.8
  TOP w0.254: U2.7 34.44,31.46 R10.2
N22387215: length 6.1
  TOP w0.254: U2.9 36.23,34.76 36.72,34.26 36.72,33.75 R15.1 R11.2
N22387217: length 3.7
  TOP w0.254: TP6.1 35.84,32.28 34.88,33.23 U2.8
N22387362: length 2.8
  TOP w0.254: TP8.1 36.72,35.21 U2.10
N22387364: length 5.9
  TOP w0.254: U2.11 37.39,35.66 38.38,34.67 R16.1 R14.2 C31.2
N22387368: length 1
  TOP w0.381: R13.2 40.62,32.64 C31.1
N22387403: length 3.2
  TOP w0.254: U2.12 38.4,36.11 C32.1
N22404559: length 6.8
  BOTTOM w0.152: R332.1 89.45,103.69 89.45,104.83 C197.1 D36.2 91.04,105.41 J18.2
N22407290: length 7.9
  BOTTOM w0.152: J18.3 93.58,106.75 94.41,105.92 D37.2 C198.1 95.62,105.34 96.16,104.8 96.16,103.61 95.74,103.18 R333.1
N22407725: length 1.3
  TOP w0.152: D55.1 96,118.43 R427.2
N22483474: length 1.9
  TOP w0.152: U12.4 159.1,84.44 R104.1
N22483498: length 0.9
  TOP w0.152: C72.1 R106.2
N22483568: length 1.9
  TOP w0.152: R105.1 159.1,80.63 U13.4
N22513317: length 2.7
  TOP w0.152: R218.2 121.71,42.16 121.72,42.16 SW2.2
N22513319: length 2.7
  TOP w0.152: SW2.3 122.98,41.09 R219.2
N22513321: length 2.7
  TOP w0.152: SW2.4 124.26,42.16 124.25,42.16 R220.2
N22513323: length 2.7
  TOP w0.152: SW3.1 129.59,43.74 R230.2
N22515068: length 2.7
  TOP w0.152: R229.2 120.44,41.09 SW2.1
N22517589: length 23.3
  TOP w0.152: J22.11 92.9,7.01 92.1,7.81 92.1,11.75 95.08,14.73 96.1,14.73 97.62,16.26 97.62,22.23 97.11,22.73 R344.2
N22517591: length 21.8
  TOP w0.152: R345.2 81.62,17.65 88.61,10.66 88.61,7.75 87.86,7.01 J22.13
N22525013: length 21.9
  TOP w0.152: J23.13 110.56,7.01 111.31,7.75 111.31,10.66 104.28,17.69 R380.2
N22525015: length 23.7
  TOP w0.152: R379.2 120.32,22.86 120.32,16.46 118.59,14.73 117.78,14.73 114.79,11.75 114.79,7.81 115.6,7.01 J23.11
N22597309: length 2.4
  TOP w0.152: v2(149.15,69.34) R461.1 R491.1
  BOTTOM w0.152: R192.2 149.97,69.34 v2(149.15,69.34)
N22610391: length 3.3
  TOP w0.152: R539.2 U40.10
N22680350: length 8.3
  TOP w0.152: 9.32,106.3 13.25,106.3 14.02,107.06 14.02,108.33 14.52,108.84 15.76,108.84 U46.5
N22680357: length 3.5
  TOP w0.152: J26.2 12.76,108.84 U46.4
N22683837: length 4.5
  TOP w0.457: U47.2 58.64,116.35 arc(58.93,117.06) 59.65,117.36 C263.1 R502.2
N22683839: length 4.2
  TOP w0.457: J27.2 D56.2 63.38,118.38 arc(63.08,117.66) C264.1 R502.1
N22683943: length 2.6
  TOP w0.152: R81.2 63.97,103.86 U47.40
N22683961: length 2.6
  TOP w0.152: R79.2 63.91,104.76 U47.41
N22683997: length 4.8
  TOP w0.457: R504.2 C265.1 51.09,117.36 arc(51.97,116.99) 52.34,116.11 U47.9
N22684003: length 4.3
  TOP w0.457: J28.2 D57.2 47.16,118.38 arc(47.46,117.66) C266.1 R504.1
N22684239: length 1.4
  TOP w0.152: R511.2 55.01,95.21 Y6.1
N22684315: length 3.9
  TOP w0.152: Y6.3 52.88,94.44 52.88,95.63 52.06,96.45 R512.1
N22685134: length 6.7
  TOP w0.152: U47.18 45.5,107.46 R85.2 44.86,106.93 43.16,106.93 R69.2
N22685150: length 6.5
  TOP w0.152: U47.17 45.49,108.36 R84.2 44.91,108.94 42.75,108.94 R70.2
N22685166: length 6.7
  TOP w0.152: R71.2 43.1,105.85 44.87,105.85 R83.2 45.58,106.56 U47.19
N22685182: length 6.8
  TOP w0.152: R72.2 43.1,104.71 44.87,104.71 R82.2 45.83,105.66 U47.20
N22685198: length 6.9
  TOP w0.152: R74.2 43.03,102.49 44.94,102.49 R80.2 46.32,103.87 48.68,103.87 U47.22
N22685204: length 6.9
  TOP w0.152: U47.21 46.07,104.76 R78.2 44.87,103.57 43.1,103.57 R76.2
N22709458: length 3.4
  TOP w0.152: U48.72 155.17,34.86 156.26,35.94 R514.2
N22710105: length 3.8
  TOP w0.152: U48.36 144.06,26.36 R515.1
N22710530: length 3.8
  TOP w0.152: U48.41 146.89,22.57 R516.2
N22712478: length 3.7
  TOP w0.152: U48.69 155.27,33.36 R517.1
N22712757: length 13.2
  TOP w0.152: R518.1 151.27,17.47 151.86,18.06 151.86,18.57 151.98,18.68 153.17,18.68 154.3,19.81 154.3,21.95 154.78,22.43 154.78,25.4 155.06,25.68 155.06,26.59 154.8,26.86 U48.56
N22714174: length 3.4
  TOP w0.152: R545.1 R521.2 145.71,52.77 U50.3
N22724008: length 2.4
  TOP w0.152: Q2.1 146.27,18.03 145.96,18.35 R524.2
N22724271: length 2.3
  TOP w0.152: R532.2 151.81,48.13 151.17,48.78 U53.5
N22724282: length 2.2
  TOP w0.152: U53.4 146.72,48.78 146.48,49.02 R533.2
N22746676: length 2.7
  TOP w0.381: Y7.1 141.35,20.31 R535.2 C294.1
N22751077: length 3.5
  TOP w0.152: D58.2 148.18,13.15 149.2,12.14 J29.18
N22751165: length 3
  TOP w0.152: D59.2 150.78,14.66 R523.1 R522.1
N22767924: length 3.3
  TOP w0.152: U20.3 R252.2
N22767926: length 7.3
  TOP w0.508: L7.1 158.63,109.18 157.53,108.08 156.06,108.08 155.17,107.19 U20.7
N22767928: length 3.5
  TOP w0.508: L7.4 155.42,109.75 R255.1 153.71,109.46 R253.1
N22767957: length 3.4
  TOP w0.508: L7.3 155.55,111.14 R256.1 153.71,111.43 R254.1
N22767970: length 3.3
  TOP w0.152: U20.2 R257.2
N22767972: length 9.6
  TOP w0.508: U20.6 157.71,106.23 159.43,107.95 160.45,107.95 161.21,108.71 161.21,111.08 160.7,111.58 L7.2
N22768026: length 2.7
  TOP w0.508: R255.2 R256.2 151.69,111.14 C104.1
N22768266: length 3.3
  TOP w0.152: U22.3 R260.2
N22768268: length 6.9
  TOP w0.508: U22.7 143.74,106.74 146.18,109.18 L8.1
N22768270: length 3.4
  TOP w0.508: L8.4 143.87,109.62 R264.1 142.03,109.34 R261.1
N22768305: length 3.5
  TOP w0.508: L8.3 143.74,111.02 R265.1 142.03,111.3 R262.1
N22768318: length 3.3
  TOP w0.152: U22.2 R263.2
N22768320: length 9.9
  TOP w0.508: L8.2 148.81,111.58 149.4,111 149.4,108.71 148.76,108.08 146.79,108.08 146.28,107.57 U22.6
N22768352: length 2.7
  TOP w0.508: C112.1 140,111.02 R265.2 R264.2
N22843605: length 2.1
  TOP w0.152: C318.1 152.45,52.77 U50.4
N22857632: length 3.8
  TOP w0.152: U48.45 148.89,22.54 R161.2
N22857662: length 4
  TOP w0.152: R162.2 148.39,23.06 U48.44
N22863110: length 206.9
  TOP w0.152: v2(160.22,39.05) R445.1 R142.2 ; R290.1 44.88,30.35 50.16,35.64 v2(63.19,35.64) ; R452.1 v2(161.08,74.55)
  ART03 w0.152: v2(160.22,39.05) 164.22,39.05 166.77,41.61 168.75,41.61 170.73,43.59 170.73,66.8 162.99,74.55 v2(161.08,74.55)
  BOTTOM w0.152: v2(63.19,35.64) 63.42,35.64 77.39,21.67 84.04,21.67 84.76,20.95 115.9,20.95 116.58,21.64 125.85,21.64 126.84,20.65 129.26,20.65 130.35,19.56 140.13,19.56 140.81,18.87 143.73,18.87 144.32,18.29 149.5,18.29 151.56,16.23 155.85,16.23 160.42,20.8 162.66,20.8 163.8,21.95 163.8,33.68 160.22,37.26 v2(160.22,39.05)
N22863348: length 258.8
  TOP w0.152: R454.1 v2(57.77,22.61) ; R453.1 v2(114.47,70.36)
  ART03 w0.152: v2(57.07,46.71) 57.07,48.13 58.29,49.35 58.29,55.8 53.26,60.83 40.66,60.83 39.95,61.54 39.95,66.95 38.55,68.35 31.54,68.35 29.43,70.46 24.2,70.46 23.08,69.34 v2(23.08,66.34) ; v2(57.77,22.61) 57.77,23.56 58.85,24.64 59.99,24.64 60.51,25.15 77.27,25.15 78.08,25.96 80.13,25.96 81.56,24.54 84.39,24.54 84.87,25.02 86.28,25.02 86.66,24.64 92.25,24.64 92.6,24.99 93.82,24.99 94.31,24.51 105.46,24.51 105.94,24.99 119.81,24.99 123.68,21.12 126.09,21.12 126.74,20.47 139.14,20.47 140.25,21.59 140.25,22.45 140.88,23.08 140.88,42.74 145.46,47.32 v2(145.46,47.5)
  BOTTOM w0.152: v2(57.77,22.61) 57.77,28.76 55.57,30.96 55.57,39.42 57.07,40.92 v2(57.07,46.71) ; R451.1 R554.2 19.93,65.32 20.95,66.34 v2(23.08,66.34) ; v2(114.47,70.36) 114.47,74.17 115.74,75.44 122.98,75.44 125.47,72.95 130.17,72.95 132.38,70.74 132.38,70.1 140.2,62.28 140.2,54.39 143.92,50.67 144.57,50.67 145.13,50.11 145.13,47.83 v2(145.46,47.5)
N22865159: length 2.6
  TOP w0.152: R555.1 64.99,31.01 U54.15
N22941387: length 3.7
  TOP w0.152: R5.2 R558.2 70.86,26.57 Q1.3
N22941439: length 2.6
  TOP w0.152: Q6.2 68.93,26.73 R559.2 R560.2
N22941491: length 3.7
  TOP w0.152: Q7.3 78.11,23.5 R561.2 R562.2
N22941543: length 2.6
  TOP w0.152: R12.2 R563.2 78.36,25.3 Q8.2
N22973519: length 2.8
  TOP w0.152: R419.1 116.31,64.01 U40.7
N22982457: length 4
  TOP w0.152: JP1.2 76.22,35.03 76.88,35.69 R567.1
N22991878: length 2.7
  TOP w0.254: R569.1 42.37,16.04 C322.2 C321.2
N23013826: length 147.9
  TOP w0.152: v2(35.75,44.49) 34.97,43.71 30.02,43.71 28.13,41.83 28.13,39.51 JP2.1 ; v2(160.19,54.61) 160.2,54.61 R571.2
  ART03 w0.152: v2(160.19,54.61) 158.67,56.13 158.67,57.4 158.03,58.04 141.78,58.04 140.76,57.02 134.79,57.02 134.16,56.39 130.73,56.39 129.21,54.86 112.39,54.86 111.86,54.33 111.86,52.65 110.21,51 108.66,51 105.03,47.37 91.46,47.37 90.5,48.34 84.71,48.34 84.3,47.93 74.9,47.93 71.83,44.86 64.31,44.86 62.45,46.71 58.64,46.71 56.49,44.55 35.81,44.55 v2(35.75,44.49)
N23013829: length 150.6
  TOP w0.152: v2(126.64,57.56) 142.57,57.56 144.06,59.05 158.03,59.05 159.3,60.33 R572.2 ; JP3.1 29.69,61.29 v2(41.07,61.29)
  ART03 w0.152: v2(71.93,49.19) 69.2,46.46 64.77,46.46 58.8,52.43 58.8,55.98 53.49,61.29 v2(41.07,61.29) ; v2(126.64,57.56) 125.65,56.57 121.92,56.57 121.59,56.9 v2(111.43,56.9)
  BOTTOM w0.152: v2(71.93,49.19) 78.11,49.19 78.96,48.34 84.91,48.34 86.43,49.86 91.51,49.86 92.1,49.28 102.89,49.28 105.03,51.41 105.03,54.15 107.77,56.9 v2(111.43,56.9)
N23945057: length 1.3
  TOP w0.152: R423.2 93.08,118.43 D50.1
N24701406: length 2
  TOP w0.152: R307.1 136.32,28.32 136.3,28.34 U28.28
N24701492: length 2.3
  TOP w0.152: R305.2 136.83,32.32 136.51,32.32 136.03,31.84 U28.35
N24701498: length 2.5
  TOP w0.152: U28.36 135.89,32.34 137.08,33.53 R304.2
N24701504: length 2.2
  TOP w0.152: R303.1 133.61,35.84 U28.37
N24926165: length 8.3
  BOTTOM w0.381: R334.2 86.69,103.18 86.18,103.69 86.18,104.83 86.69,105.34 C196.1 C195.1 D35.2 88.95,106.43 88.5,106.87 J18.1
N25388780: length 7.4
  BOTTOM w0.505: J21.2 D39.2 J20.1
N25609213: length 1.3
  TOP w0.152: D53.1 101.34,118.43 R424.2
N25609260: length 1.3
  TOP w0.152: D54.1 98.67,118.43 R426.2

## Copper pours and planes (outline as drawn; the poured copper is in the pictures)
AVCC_1V2 on TOP: 152.19,22.1 152.32,21.97 153.08,21.97 153.21,22.1 153.21,23.11 153.08,23.24 152.32,23.24 152.19,23.11
AVCC_1V2 on BOTTOM: 153.72,32.26 153.72,28.57 153.84,28.45 154.86,28.45 155.24,28.07 155.24,26.42 152.32,23.5 152.32,22.86 152.45,22.73 153.21,22.73 156.26,25.78 156.26,31.5 155.49,32.26
GND on TOP (solid shape): outline of 474 points within 7.79,23.11 62.78,53.72
GND on TOP: 115.67,59.26 115.49,59.44 115.49,62.05 111.15,66.4 111.15,71.45 111.63,71.93 114.32,71.93 114.52,71.73 114.52,71.04 114.3,70.82 114.02,70.82 113.89,70.69 113.89,70.08 114.19,69.77 117.32,69.77 117.52,69.57 117.52,68.73 117.93,68.33 120.95,68.33 121.2,68.07 121.2,67.44 121.08,67.31 115.69,67.31 115.36,66.98 115.36,63.47 115.77,63.07 120.09,63.07 120.34,62.81 120.34,61.24 119.81,60.71 116.81,60.71 116.43,60.33 116.43,59.54 116.15,59.26
GND on TOP: 80.44,7.24 77.64,7.24 77.14,7.75 77.14,8.76 77.39,9.02 80.31,9.02 80.44,8.89
GND on TOP: 126.79,22.35 126.79,21.34 126.89,21.23 129.61,21.23 129.84,21.46 129.84,22.23 129.59,22.48 126.92,22.48
GND on TOP: 139.37,90.55 139.35,90.56 136.2,90.56 135.17,91.59 135.17,96.65 135.3,96.77 136.95,96.77 137.21,96.52 137.21,93.6 138.86,91.95 142.79,91.95 142.92,91.82 142.92,90.81 142.67,90.55
GND on TOP: 65.58,112.14 65.03,112.69 65.03,114.74 67.61,117.32 67.61,124.26 67.85,124.49 104.19,124.49 104.19,120.02 103.81,119.63 91.61,119.63 91.23,119.25 91.23,116.79 91.59,116.43 92.45,116.43 92.58,116.31 92.58,115.37 92.4,115.19 90.22,115.19 89.84,114.81 89.84,111 90.09,110.74 90.6,110.74 90.6,106.17 88.06,103.63 87.17,103.63 86.41,104.39 86.41,112.27 86.15,112.52 76.25,112.52 75.87,112.14 75.87,107.82 76.25,107.44 77.01,107.44 77.01,106.3 76.37,105.66 76.37,103.89 76.75,103.5 78.66,103.5 78.79,103.38 78.79,102.87 78.66,102.74 76.12,102.74 75.79,102.41 75.79,100.03 75.38,99.62 67.26,99.62 66.62,100.25 66.62,106.02 65.58,107.06
GND on TOP: 169.72,77.72 171.75,77.72 172,77.47 172,76.71 171.62,76.33 169.59,76.33 169.46,76.45 169.46,77.47
GND on TOP: 164.38,55.75 164.38,55.12 164.77,54.74 171.75,54.74 172,54.99 172,55.63 171.75,55.88 164.51,55.88
GND on TOP: 113.2,98.3 113.58,97.92 113.58,93.55 113.2,93.17 111.38,93.17 109.11,95.43 104.36,95.43 103.7,96.09 103.7,98.53 103.88,98.7 108.56,98.7 108.96,98.3
GND on TOP: outline of 109 points within 157.35,9.27 172.59,46.74
GND on TOP: 8.43,52.96 15.67,52.96 15.79,52.83 15.79,52.07 15.67,51.94 13.2,51.94 12.77,51.51 11.1,51.51 10.84,51.26 10.84,50.29 10.59,50.04 8.43,50.04
GND on TOP: 122.47,22.81 123.52,22.81 123.77,23.06 123.77,24.46 123.21,25.02 121.28,25.02 121.03,24.77 121.03,22.38 121.15,22.25 121.92,22.25
GND on TOP: 85.3,38.61 85.3,37.72 85.43,37.59 86.7,37.59 86.83,37.72 86.83,38.48 86.7,38.61
GND on TOP: 73.07,13.08 74.98,13.08 75.36,13.46 77.9,13.46 78.28,13.08 78.28,11.3 78.66,10.92 79.93,10.92 80.18,11.18 80.18,18.95 80.08,19.05 76.22,19.05 76.12,18.95 76.12,15.75 75.48,15.11 72.31,15.11 72.18,14.99 72.18,10.08 72.28,9.98 72.64,9.98 72.74,10.08 72.74,10.69 73.02,10.97 73.73,10.97 73.81,11.05 73.81,11.94 73.63,12.12 73.12,12.12 72.97,12.27 72.97,12.98
GND on TOP: 18.59,13.46 18.21,13.84 18.21,16.51 19.22,17.53 19.25,17.53 20.47,18.75 20.47,27.91 20.87,28.32 22.65,28.32 22.91,28.07 22.91,25.27 22.14,24.51 22.14,23.75 22.02,23.62 22.02,14.22 21.26,13.46
GND on TOP: 98.85,16.38 103.17,16.38 103.68,16.89 103.68,25.78 101.9,27.56 98.6,27.56 97.84,26.8 97.84,22.99 98.6,22.23 98.6,16.64
GND on TOP: outline of 216 points within 8.3,61.72 65.32,124.21
GND on TOP: 160.19,90.14 159.81,90.53 159.81,98.73 160.19,99.11 161.31,99.11 162.18,99.97 166.62,99.97 166.77,99.82 166.77,97.97 167.2,97.54 171.95,97.54 172.61,96.88 172.61,90.4 172.36,90.14
GND on TOP: 80.06,106.68 81.07,106.68 81.33,106.93 81.33,107.57 81.07,107.82 79.93,107.82 79.8,107.7 79.8,106.93
GND on TOP: 122.47,96.65 122.47,93.6 122.73,93.34 124.25,93.34 124.51,93.6 124.51,96.52 124.25,96.77 122.6,96.77
GND on TOP: 136.67,11.63 137.51,11.63 137.89,12.01 137.89,16.48 139.06,17.65 141.6,17.65 142.72,16.54 142.72,15.19 143,14.91 145.82,14.91 146.02,15.11 146.02,16.18 145.46,16.74 143.76,16.74 143.02,17.48 143.02,17.81 143.33,18.11 144.34,18.11 144.42,18.19 144.42,18.62 144.24,18.8 139.49,18.8 138.38,19.91 138.38,21.95 139.95,23.52 139.95,24.13 139.62,24.46 139.62,28.65 139.37,28.91 138.1,28.91 137.77,28.57 137.77,27.84 137.56,27.64 136.9,27.64 136.72,27.46 136.72,26.64 136.34,26.26 136.34,20.88 136.47,20.75 137.11,20.75 137.18,20.68 137.18,19.61 136.44,18.87 136.44,11.86
GND on TOP: 116,96.9 116,91.31 116.12,91.19 116.89,91.19 117.14,91.44 117.14,94.36 116.89,94.61 116.89,96.9 116.76,97.03 116.12,97.03
GND on TOP: 108.59,38.61 108.59,37.72 108.72,37.59 109.99,37.59 110.18,37.78 110.18,37.97 110.38,38.18 110.44,38.18 110.56,38.3 110.56,38.58 110.51,38.63 109.83,38.63 109.8,38.61
GND on TOP: 122.6,19.23 123.54,19.23 123.74,19.02 123.74,18.49 123.54,18.29 120.82,18.29 120.7,18.41 120.7,20.32 120.82,20.45 121.38,20.45
GND on TOP: 163.37,86.11 163.11,85.85 161.84,85.85 161.59,86.11 161.59,87.25 161.72,87.38 163.24,87.38 163.37,87.25
GND on TOP: 43.73,115.57 42.46,116.84 42.46,124.49 66.82,124.49 66.98,124.33 66.98,117.35 65.2,115.57
GND on TOP: 124.51,71.88 124.51,71.5 124.76,71.25 127.43,71.25 127.68,71.5 127.68,71.88 127.55,72.01 124.63,72.01
GND on TOP: 164.38,65.91 164.38,64.9 164.64,64.64 171.75,64.64 172,64.9 172,65.79 171.62,66.17 164.64,66.17
GND on TOP: 169.72,80.39 171.75,80.39 172,80.14 172,79.76 171.75,79.5 169.72,79.5 169.59,79.38 169.08,79.38 168.96,79.5 168.96,80.52 169.08,80.64 169.46,80.64
GND on TOP: 128.82,96.77 128.82,91.95 128.57,91.69 128.57,91.19 128.7,91.06 129.59,91.06 129.71,91.19 129.71,92.84 129.97,93.09 129.97,94.49 129.71,94.74 129.71,96.52 129.46,96.77
GND on TOP: 104.69,39.12 104.82,39.24 104.82,40.56 104.59,40.79 103.88,40.79 103.77,40.68 103.77,39.24 103.9,39.12
GND on TOP: 133.63,32.87 128.16,32.87 127.55,32.26 127.55,26.77 128.04,26.29 133.65,26.29 134.16,26.8 134.16,32.33
GND on TOP: 124,59.56 125.32,59.56 125.73,59.97 125.73,62.94 125.29,63.37 125.01,63.37 124.63,63.75 124.63,65.53 124.89,65.79 129.99,65.79 130.32,66.12 130.32,67.54 130.02,67.84 129.59,67.84 129.05,67.31 124.63,67.31 124.51,67.44 124.51,68.2 124.63,68.33 127.71,68.33 128.11,68.73 128.11,68.76 128.22,68.86 130.12,68.86 130.37,69.11 130.37,69.82 130.63,70.08 134.49,70.08 135.3,69.27 135.3,60.68 134.82,60.2 128.82,60.2 128.14,59.51 128.14,58.57 127.89,58.32 125.8,58.32 125.27,57.78 123.8,57.78 123.69,57.89 123.69,59.26
GND on TOP: 145.59,34.87 152.5,34.87 153.16,34.21 153.16,26.95 152.8,26.59 145.39,26.59 145.13,26.85 145.13,34.42
GND on TOP: 20.62,88.9 20.62,87.5 20.75,87.38 23.29,87.38 23.41,87.5 23.41,88.9 23.29,89.03 20.75,89.03
GND on TOP: 28.24,54.74 28.24,55.63 28.62,56.01 32.69,56.01 33.32,56.64 37.13,56.64 37.26,56.77 38.15,56.77 38.53,56.39 45.03,56.39 45.31,56.11 45.31,56.08 45.39,56.01 45.39,52.7 45.87,52.22 45.87,48.67 46.38,48.16 48.94,48.16 49.12,47.98 49.12,45.36 48.61,44.86 35.33,44.86 34.62,44.15 29.89,44.15 29.28,43.54 27.3,43.54 26.59,44.25 26.59,54.33 26.74,54.48 27.99,54.48
GND on TOP: outline of 114 points within 48.31,8.15 70.53,27.3
